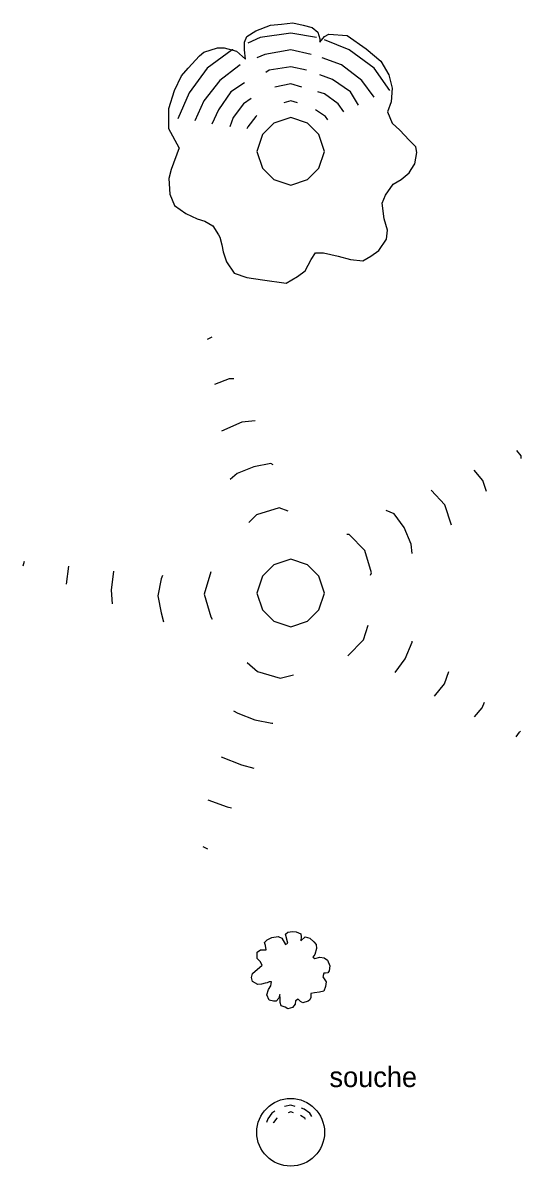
# Model space of a CAD drawing. Extents: x -1.5 to 18.2, y -66.6 to 3.3.
# Drawn here: x 10.85 to 18.21, y -14.49 to 2.4 of the extents above; entities that cross this region are included whole.
import ezdxf

# ---------------------------------------------------------------- set-up
doc = ezdxf.new("R2010")
doc.units = 0
doc.layers.add('SOL_ARBRE', color=7, linetype='Continuous')

# ---------------------------------------------------------------- blocks, each defined once
blk = doc.blocks.new('ARBRE_FEUILLU')
for points in [[(-1.647, 0.051), (-1.797, 0.333), (-1.797, 0.633), (-1.714, 0.9), (-1.614, 1.115), (-1.514, 1.232), (-1.347, 1.415), (-1.282, 1.465), (-1.082, 1.532), (-0.982, 1.532), (-0.798, 1.482), (-0.665, 1.365), (-0.683, 1.5), (-0.683, 1.614), (-0.648, 1.699), (-0.516, 1.782), (-0.298, 1.864), (-0.133, 1.882), (0.034, 1.899), (0.184, 1.864), (0.316, 1.832), (0.401, 1.764), (0.433, 1.664), (0.433, 1.614), (0.501, 1.699), (0.566, 1.732), (0.833, 1.714), (1.115, 1.515), (1.332, 1.332), (1.45, 1.133), (1.5, 0.933), (1.482, 0.733), (1.432, 0.583), (1.5, 0.416), (1.614, 0.316), (1.749, 0.166), (1.849, 0.066)], [(0.383, 1.682), (0.001, 1.749), (-0.448, 1.682), (-0.633, 1.599)], [(1.465, 0.9), (1.232, 1.232), (0.865, 1.5), (0.501, 1.649)], [(-0.848, 1.5), (-0.865, 1.5), (-1.232, 1.232), (-1.497, 0.865), (-1.664, 0.483)], [(0.301, 1.432), (0.001, 1.5), (-0.383, 1.432), (-0.498, 1.382)], [(1.232, 0.8), (1.05, 1.05), (0.75, 1.282), (0.466, 1.382)], [(-0.748, 1.282), (-0.765, 1.265), (-1.047, 1.05), (-1.282, 0.75), (-1.414, 0.451)], [(0.234, 1.2), (0.001, 1.25), (-0.316, 1.2), (-0.366, 1.165)], [(-0.683, 1.015), (-0.883, 0.883), (-1.065, 0.616), (-1.165, 0.401)], [(1, 0.683), (0.883, 0.883), (0.616, 1.065), (0.433, 1.133)], [(0.166, 0.95), (0.001, 1), (-0.233, 0.95)], [(0.783, 0.583), (0.701, 0.701), (0.501, 0.85), (0.401, 0.883)], [(-0.583, 0.783), (-0.698, 0.701), (-0.848, 0.501), (-0.898, 0.366)], [(0.101, 0.716), (0.001, 0.75), (-0.099, 0.716)], [(-0.498, 0.533), (-0.516, 0.516), (-0.633, 0.366), (-0.648, 0.333)], [(0.551, 0.466), (0.516, 0.516), (0.366, 0.616)], [(0.501, 0.001), (0.416, 0.251), (0.251, 0.416), (0.001, 0.501), (-0.248, 0.416), (-0.416, 0.251), (-0.498, 0.001), (-0.416, -0.248), (-0.248, -0.416), (0.001, -0.498), (0.251, -0.416), (0.416, -0.248), (0.501, 0.001)], [(-1.647, 0.051), (-1.764, -0.266), (-1.797, -0.398), (-1.782, -0.633), (-1.714, -0.798), (-1.547, -0.915), (-1.382, -0.997), (-1.265, -1.032), (-1.147, -1.097), (-1.065, -1.232), (-1.047, -1.265), (-1.015, -1.382), (-0.997, -1.482), (-0.948, -1.632), (-0.833, -1.797), (-0.648, -1.864), (-0.416, -1.896), (-0.066, -1.946), (0.101, -1.846), (0.216, -1.764), (0.301, -1.597), (0.366, -1.497), (0.483, -1.497), (0.701, -1.547), (0.883, -1.597), (1.065, -1.614), (1.182, -1.547), (1.3, -1.464), (1.415, -1.297), (1.432, -1.165), (1.382, -0.997), (1.35, -0.765), (1.4, -0.648), (1.515, -0.483), (1.632, -0.416), (1.749, -0.316), (1.782, -0.266), (1.832, -0.183), (1.864, -0.016), (1.849, 0.066)]]:
    blk.add_lwpolyline(points)
blk = doc.blocks.new('ARBRE_CONIFERE')
for points in [[(-1.165, 3.78), (-1.233, 3.745)], [(-0.841, 3.165), (-0.909, 3.165), (-1.126, 3.08)], [(-0.523, 2.544), (-0.722, 2.526), (-1.022, 2.394)], [(3.404, 1.991), (3.404, 2.026), (3.339, 2.109)], [(-0.26, 1.897), (-0.293, 1.915), (-0.543, 1.865), (-0.792, 1.765), (-0.892, 1.68)], [(2.89, 1.499), (2.84, 1.666), (2.708, 1.816)], [(2.377, 1.006), (2.277, 1.305), (2.077, 1.523)], [(-0.038, 1.209), (-0.171, 1.259), (-0.505, 1.159), (-0.62, 1.044)], [(1.793, 0.587), (1.778, 0.722), (1.678, 0.971), (1.528, 1.171), (1.411, 1.221)], [(1.181, 0.265), (1.196, 0.3), (1.097, 0.632), (0.864, 0.865), (0.832, 0.865)], [(-3.937, 0.468), (-3.955, 0.4)], [(-3.28, 0.399), (-3.313, 0.134)], [(0.501, 0.001), (0.416, 0.251), (0.251, 0.416), (0.001, 0.501), (-0.248, 0.416), (-0.416, 0.251), (-0.498, 0.001), (-0.416, -0.248), (-0.248, -0.416), (0.001, -0.498), (0.251, -0.416), (0.416, -0.248), (0.501, 0.001)], [(-2.616, 0.326), (-2.651, 0.043), (-2.634, -0.156)], [(-1.895, 0.259), (-1.91, 0.209), (-1.96, -0.04), (-1.91, -0.29), (-1.878, -0.425)], [(-1.179, 0.315), (-1.279, -0.017), (-1.179, -0.351), (-1.161, -0.384)], [(0.844, -0.924), (1.076, -0.691), (1.143, -0.474)], [(1.543, -1.173), (1.693, -0.973), (1.793, -0.724), (1.793, -0.709)], [(-0.641, -1.025), (-0.491, -1.158), (-0.157, -1.258), (0.043, -1.208)], [(2.123, -1.523), (2.273, -1.34), (2.338, -1.158)], [(2.713, -1.828), (2.83, -1.695), (2.863, -1.61)], [(-0.846, -1.739), (-0.778, -1.771), (-0.529, -1.871), (-0.279, -1.921), (-0.264, -1.921)], [(3.33, -2.123), (3.38, -2.055), (3.395, -2.038)], [(-1.026, -2.42), (-0.727, -2.538), (-0.542, -2.587)], [(-1.222, -3.056), (-0.94, -3.155), (-0.873, -3.173)], [(-1.298, -3.745), (-1.23, -3.777)]]:
    blk.add_lwpolyline(points)
blk = doc.blocks.new('ARBUSTE')
blk.add_lwpolyline([(-0.452, 0.127), (-0.497, 0.172), (-0.496, 0.267), (-0.446, 0.301), (-0.361, 0.301), (-0.371, 0.361), (-0.385, 0.406), (-0.345, 0.445), (-0.28, 0.48), (-0.185, 0.494), (-0.13, 0.474), (-0.076, 0.378), (-0.041, 0.398), (-0.075, 0.533), (-0.04, 0.558), (0.025, 0.572), (0.08, 0.567), (0.15, 0.536), (0.155, 0.491), (0.149, 0.432), (0.214, 0.491), (0.284, 0.471), (0.344, 0.42), (0.378, 0.38), (0.383, 0.32), (0.357, 0.23), (0.327, 0.191), (0.357, 0.17), (0.432, 0.19), (0.497, 0.179), (0.546, 0.149), (0.581, 0.064), (0.57, -0.011), (0.55, -0.041), (0.515, -0.045), (0.49, -0.045), (0.475, -0.1), (0.524, -0.175), (0.514, -0.24), (0.488, -0.31), (0.428, -0.324), (0.353, -0.334), (0.298, -0.348), (0.298, -0.403), (0.282, -0.438), (0.257, -0.458), (0.182, -0.482), (0.147, -0.462), (0.113, -0.427), (0.073, -0.456), (0.067, -0.501), (0.027, -0.551), (-0.043, -0.57), (-0.083, -0.55), (-0.138, -0.53), (-0.157, -0.48), (-0.157, -0.425), (-0.161, -0.36), (-0.177, -0.415), (-0.212, -0.459), (-0.252, -0.459), (-0.317, -0.444), (-0.351, -0.363), (-0.325, -0.289), (-0.295, -0.234), (-0.285, -0.174), (-0.315, -0.174), (-0.345, -0.189), (-0.375, -0.193), (-0.43, -0.208), (-0.485, -0.213), (-0.564, -0.167), (-0.579, -0.107), (-0.563, -0.052), (-0.423, 0.071), (-0.452, 0.127)])
blk = doc.blocks.new('SOUCHE')
for points in [[(0.067, 0.381), (0.001, 0.401), (-0.093, 0.381)], [(0.314, 0.234), (0.281, 0.281), (0.201, 0.341), (0.161, 0.354)], [(-0.233, 0.314), (-0.279, 0.281), (-0.339, 0.201), (-0.359, 0.147)], [(-0.199, 0.214), (-0.206, 0.207), (-0.253, 0.147), (-0.259, 0.134)], [(0.041, 0.287), (0.001, 0.301), (-0.039, 0.287)], [(0.221, 0.187), (0.207, 0.207), (0.147, 0.247)]]:
    blk.add_lwpolyline(points)
blk.add_circle((0, 0), 0.5)
blk.add_text('souche', height=0.3).set_placement((0.573, 0.668))

msp = doc.modelspace()

# ---------------------------------------------------------------- block references
at = {"layer": 'SOL_ARBRE'}
for name, p in [('ARBRE_FEUILLU', (14.805, 0.5)), ('ARBRE_CONIFERE', (14.805, -6.025)), ('ARBUSTE', (14.805, -11.594)), ('SOUCHE', (14.805, -13.99))]:
    msp.add_blockref(name, p, dxfattribs=at)

doc.saveas('drawing.dxf')
